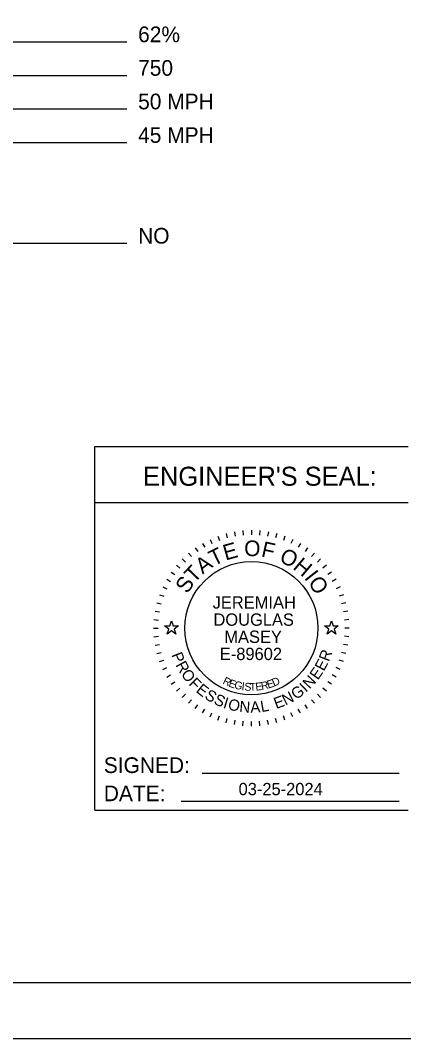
# Model space of a CAD drawing. Extents: x -38.2 to 41.9, y -4 to 24.9.
# Drawn here: x 6.68 to 10.11, y 0 to 9.1 of the extents above; entities that cross this region are included whole.
import ezdxf

# ---------------------------------------------------------------- set-up
doc = ezdxf.new("R2010")
doc.units = 0
for name, color, linetype in [('SH_Border', 7, 'Continuous'), ('SH_Cut_Line', 7, 'Continuous'), ('SH_Data', 7, 'Continuous'), ('SH_Text', 7, 'Continuous')]:
    doc.layers.add(name, color=color, linetype=linetype)

msp = doc.modelspace()

# ---------------------------------------------------------------- linework, layer by layer
at = {"layer": 'SH_Border'}
msp.add_lwpolyline([(1.5, 21.5), (33.5, 21.5), (33.5, 0.5), (1.5, 0.5)], close=True, dxfattribs=at)
at = {"layer": 'SH_Cut_Line'}
msp.add_lwpolyline([(0, 0), (34, 0), (34, 22), (0, 22)], close=True, dxfattribs=at)
at = {"layer": 'SH_Data'}
for p, q in [((7.6368, 8.9062), (4.6037, 8.9062)), ((7.6368, 8.6062), (4.1885, 8.6062)), ((7.6368, 8.3062), (3.346, 8.3062)), ((7.6368, 8.0062), (3.2422, 8.0062)), ((7.6368, 7.1062), (3.2669, 7.1062)), ((7.35, 2.0417), (7.35, 5.2917)), ((7.35, 5.2917), (10.15, 5.2917)), ((7.35, 4.7917), (10.15, 4.7917)), ((8.3802, 4.4617), (8.3971, 4.4254)), ((8.4507, 4.4909), (8.4644, 4.4533)), ((8.5235, 4.5138), (8.5339, 4.4752)), ((8.5981, 4.5304), (8.605, 4.491)), ((8.6737, 4.5403), (8.6772, 4.5005)), ((8.75, 4.5437), (8.75, 4.5037)), ((8.8263, 4.5403), (8.8228, 4.5005)), ((8.9019, 4.5304), (8.895, 4.491)), ((8.9765, 4.5138), (8.9661, 4.4752)), ((9.0493, 4.4909), (9.0356, 4.4533)), ((9.1198, 4.4617), (9.1029, 4.4254)), ((8.2481, 4.3854), (8.2711, 4.3527)), ((8.3125, 4.4264), (8.3325, 4.3918)), ((9.1875, 4.4264), (9.1675, 4.3918)), ((9.2519, 4.3854), (9.2289, 4.3527)), ((8.1313, 4.2874), (8.1596, 4.2591)), ((8.1876, 4.339), (8.2133, 4.3083)), ((9.3124, 4.339), (9.2867, 4.3083)), ((9.3687, 4.2874), (9.3404, 4.2591)), ((8.0797, 4.2311), (8.1104, 4.2054)), ((9.4203, 4.2311), (9.3896, 4.2054)), ((7.9922, 4.1062), (8.0269, 4.0862)), ((8.0332, 4.1705), (8.066, 4.1476)), ((9.4668, 4.1705), (9.434, 4.1476)), ((9.5078, 4.1062), (9.4731, 4.0862)), ((7.957, 4.0385), (7.9932, 4.0215)), ((9.543, 4.0385), (9.5068, 4.0215)), ((7.9278, 3.9679), (7.9654, 3.9542)), ((9.5722, 3.9679), (9.5346, 3.9542)), ((7.9048, 3.8951), (7.9435, 3.8848)), ((9.5952, 3.8951), (9.5565, 3.8848)), ((7.8783, 3.7449), (7.9182, 3.7414)), ((7.8883, 3.8206), (7.9277, 3.8137)), ((9.6117, 3.8206), (9.5723, 3.8137)), ((9.6217, 3.7449), (9.5818, 3.7414)), ((7.875, 3.6687), (7.915, 3.6687)), ((9.625, 3.6687), (9.585, 3.6687)), ((7.8783, 3.5924), (7.9182, 3.5959)), ((9.6217, 3.5924), (9.5818, 3.5959)), ((7.8883, 3.5167), (7.9277, 3.5237)), ((9.6117, 3.5167), (9.5723, 3.5237)), ((7.9048, 3.4422), (7.9435, 3.4525)), ((7.9278, 3.3694), (7.9654, 3.3831)), ((9.5722, 3.3694), (9.5346, 3.3831)), ((9.5952, 3.4422), (9.5565, 3.4525)), ((7.957, 3.2989), (7.9932, 3.3158)), ((9.543, 3.2989), (9.5068, 3.3158)), ((7.9922, 3.2312), (8.0269, 3.2512)), ((8.0332, 3.1668), (8.066, 3.1897)), ((9.4668, 3.1668), (9.434, 3.1897)), ((9.5078, 3.2312), (9.4731, 3.2512)), ((8.0797, 3.1062), (8.1104, 3.1319)), ((9.4203, 3.1062), (9.3896, 3.1319)), ((8.1313, 3.0499), (8.1596, 3.0782)), ((8.1876, 2.9984), (8.2133, 3.029)), ((9.3124, 2.9984), (9.2867, 3.029)), ((9.3687, 3.0499), (9.3404, 3.0782)), ((8.2481, 2.9519), (8.2711, 2.9847)), ((8.3125, 2.9109), (8.3325, 2.9455)), ((9.1875, 2.9109), (9.1675, 2.9455)), ((9.2519, 2.9519), (9.2289, 2.9847)), ((8.3802, 2.8756), (8.3971, 2.9119)), ((8.4507, 2.8464), (8.4644, 2.884)), ((8.5235, 2.8235), (8.5339, 2.8621)), ((8.5981, 2.807), (8.605, 2.8463)), ((8.6737, 2.797), (8.6772, 2.8368)), ((8.75, 2.7937), (8.75, 2.8337)), ((8.8263, 2.797), (8.8228, 2.8368)), ((8.9019, 2.807), (8.895, 2.8463)), ((8.9765, 2.8235), (8.9661, 2.8621)), ((9.0493, 2.8464), (9.0356, 2.884)), ((9.1198, 2.8756), (9.1029, 2.9119)), ((7.35, 2.0417), (10.15, 2.0417))]:
    msp.add_line(p, q, dxfattribs=at)
msp.add_circle((8.75, 3.6687), 0.595, dxfattribs=at)
at = {"layer": 'SH_Text'}
for p, q in [((8.3083, 2.3742), (10.0713, 2.3742)), ((8.1221, 2.1222), (10.0713, 2.1222))]:
    msp.add_line(p, q, dxfattribs=at)
for points in [[(7.9736, 3.6886), (8.0205, 3.6886), (8.035, 3.7332), (8.0495, 3.6886), (8.0964, 3.6886), (8.0585, 3.661), (8.073, 3.6164), (8.035, 3.644), (7.997, 3.6164), (8.0115, 3.661)], [(9.4036, 3.6886), (9.4505, 3.6886), (9.465, 3.7332), (9.4795, 3.6886), (9.5264, 3.6886), (9.4885, 3.661), (9.503, 3.6164), (9.465, 3.644), (9.427, 3.6164), (9.4415, 3.661)]]:
    msp.add_lwpolyline(points, close=True, dxfattribs=at)

# ---------------------------------------------------------------- texts
at = {"layer": 'SH_Data'}
for s, height, rotation, p in [('T', 0.14, 25.71674, (8.4116, 4.2205)), ('E', 0.14, 15.75706, (8.5184, 4.2725)), ('O', 0.14, 359.78119, (8.6847, 4.3129)), ('F', 0.14, 347.43619, (8.8311, 4.3104)), ('O', 0.14, 332.25863, (8.9898, 4.2702)), ('A', 0.14, 36.47472, (8.3134, 4.1468)), ('H', 0.14, 319.91363, (9.1132, 4.2048)), ('T', 0.14, 46.4344, (8.2383, 4.0651)), ('I', 0.14, 308.36695, (9.2165, 4.117)), ('S', 0.14, 57.19238, (8.1781, 3.9701)), ('O', 0.14, 303.14906, (9.2521, 4.0775)), ('R', 0.1, 69.23216, (9.4419, 3.364)), ('P', 0.1, 291.49398, (8.0323, 3.4307)), ('R', 0.1, 298.73106, (8.069, 3.3404)), ('E', 0.1, 61.99508, (9.3976, 3.2785)), ('O', 0.1, 306.46664, (8.1155, 3.257)), ('E', 0.1, 54.75801, (9.3433, 3.2)), ('F', 0.1, 314.7068, (8.1843, 3.1669)), ('R', 0.07, 334.48695, (8.4875, 3.1737)), ('E', 0.07, 341.03996, (8.5406, 3.1487)), ('G', 0.07, 347.47515, (8.5914, 3.1305)), ('R', 0.07, 11.91844, (8.8425, 3.116)), ('E', 0.07, 17.68363, (8.8998, 3.1288)), ('D', 0.07, 23.30524, (8.951, 3.1457)), ('N', 0.1, 47.02243, (9.2702, 3.1194)), ('E', 0.1, 321.43929, (8.2478, 3.1035)), ('S', 0.1, 328.67637, (8.3243, 3.0439)), ('I', 0.07, 353.78581, (8.6591, 3.1155)), ('S', 0.07, 356.89262, (8.6858, 3.1115)), ('T', 0.07, 3.00609, (8.7357, 3.1073)), ('E', 0.07, 6.01169, (8.7889, 3.1099)), ('N', 0.1, 27.31129, (9.0545, 2.9762)), ('G', 0.1, 35.04687, (9.1481, 3.0257)), ('I', 0.1, 43.28703, (9.2368, 3.09)), ('S', 0.1, 335.91345, (8.4064, 2.9953)), ('I', 0.1, 343.15053, (8.4906, 2.9583)), ('O', 0.1, 346.88592, (8.5339, 2.9438)), ('N', 0.1, 355.12608, (8.6388, 2.9204)), ('A', 0.1, 2.86166, (8.7423, 2.9123)), ('L', 0.1, 10.09874, (8.8394, 2.9177)), ('E', 0.1, 20.07421, (8.9712, 2.9457))]:
    msp.add_text(s, height=height, rotation=rotation, dxfattribs=at).set_placement(p)
for s, p in [('JEREMIAH', (8.4033, 3.8436)), ('DOUGLAS', (8.4104, 3.6903)), ('MASEY', (8.5073, 3.537)), ('E-89602', (8.4672, 3.3837))]:
    msp.add_text(s, height=0.11, dxfattribs=at).set_placement(p)
at = {"layer": 'SH_Text'}
for s, height, p in [('62%', 0.14, (7.7368, 8.9062)), ('750', 0.14, (7.7368, 8.6062)), ('50 MPH', 0.14, (7.7368, 8.3062)), ('45 MPH', 0.14, (7.7368, 8.0062)), ('NO', 0.14, (7.7368, 7.1062)), ("ENGINEER'S SEAL:", 0.17, (7.7808, 4.9417)), ('SIGNED:', 0.14, (7.43, 2.3742)), ('03-25-2024', 0.11, (8.6351, 2.1758)), ('DATE:', 0.14, (7.43, 2.1222))]:
    msp.add_text(s, height=height, dxfattribs=at).set_placement(p)

doc.saveas('drawing.dxf')
